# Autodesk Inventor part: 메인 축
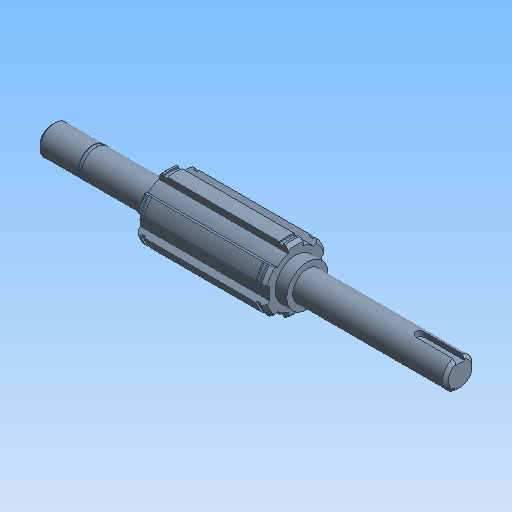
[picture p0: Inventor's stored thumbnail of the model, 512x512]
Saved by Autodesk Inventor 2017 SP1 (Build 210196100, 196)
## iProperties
Created: 2021-07
Part Number: 메인 축
Document SubType Name: 모델링
Designer: mdu
Mass: 168.566 g
Surface Area: 72.5104 cm^2
Volume: 21.4461 cm^3
Density: 7.86 g/cm^3
Material: 강철, 연강
Appearance: 연한 강청색
변환 표준: STEP AP214IS
파일 이름: C:\Users\SeoGD\Desktop\?쒗뿕\硫붿씤 異?.stp
전처리기: Build: 253, Release: 2010 SP1 - Date: Wed 07/29/2009
전송 단위: 밀리미터
불확실성: 0.01
Author: mdu
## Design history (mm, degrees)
sketch "스케치1"
  geometry: L1 (-69.5, 0)-(69.5, 0); L2 (69.5, 0)-(69.5, 5); L3 (69.5, 5)-(55.5, 5); L4 (55.5, 5)-(55.5, 4.8); L5 (55.5, 4.8)-(54.35, 4.8); L6 (54.35, 4.8)-(54.35, 5); L7 (54.35, 5)-(30.5, 5); L8 (30.5, 5)-(30.5, 9); L9 (30.5, 9)-(-13.5, 9); L10 (-13.5, 9)-(-13.5, 7); L11 (-13.5, 7)-(-17.5, 7); L12 (-17.5, 7)-(-17.5, 5); L13 (-17.5, 5)-(-69.5, 5); L14 (-69.5, 5)-(-69.5, 0); 2 further points
  constraints: 28 end point, 9 parallel, 4 collinear, 2 perpendicular, 1 coincident, 1 horizontal, 1 midpoint
  dimensions: "d2" = 1.15 distance between parallel lines of L6 L4; "d3" = 10 diameter of L3 L1; "d4" = 9.6 diameter of L5 L1; "d6" = 44 distance between parallel lines of L10 L8; "d7" = 4 distance between parallel lines of L12 L10; "d8" = 14 diameter of L11 L1; "d9" = 18 diameter of L9 L1; "d33" = 52 distance from line of L12.end L14; "d37" = 39 distance between parallel lines of L8 L2; "d38" = 14 distance between parallel lines of L2 L4
revolve "회전1" sketch "스케치1" stored, may be unused: angle "d10" = 90 deg
sketch "스케치2"
  geometry: L1 (2.5, 10.712)-(2.5, 8.646); L2 (-2.5, 10.712)-(-2.5, 8.646); A1 r 9 centre (0, 0) between (2.5, 8.646) and (-2.5, 8.646) reference; A2 r 11 centre (0, 0) between (2.5, 10.712) and (-2.5, 10.712); 1 further point
  constraints: 4 end point, 4 point on circle, 2 parallel, 1 centre point, 1 coincident, 1 vertical
  dimensions: "d11" = 22 diameter of A2; "d12" = 5 distance between parallel lines of L1 L2
extrude "돌출1" join sketch "스케치2" stored distance "d13" = 10; taper "d14" = 0 deg
chamfer "모따기1" distance "d15" = 1; stored, may be unused: second distance "d16" = 2, angle "d17" = 45 deg
node "작업 평면1"
node "작업 평면2"
sketch "스케치3"
  geometry: L1 (2.5, 10.712)-(2.5, 10.198); L2 (-2.5, 10.712)-(-2.5, 10.198); A1 r 11 centre (0, 0) between (2.5, 10.712) and (-2.5, 10.712) reference; A2 r 10.5 centre (0, 0) between (2.5, 10.198) and (-2.5, 10.198); 1 further point
  constraints: 4 end point, 2 point on circle, 1 centre point, 1 coincident, 1 parallel, 1 vertical
  dimensions: "d19" = 21 diameter of A2
extrude "돌출2" cut sketch "스케치3" distance "d20" = 1.35; taper "d21" = 0 deg
node "작업 평면3"
sketch "스케치4"
  geometry: L1 (-26, -5)-(-26, 5) reference; L2 (-26, 1.5)-(-12.5, 1.5); L3 (-12.5, -1.5)-(-26, -1.5); A1 r 1.5 centre (-12.5, 0) between (-12.5, -1.5) and (-12.5, 1.5); 2 further points
  constraints: 4 end point, 2 perpendicular, 2 point on circle, 2 point on line, 2 tangent, 1 centre point, 1 horizontal alignment, 1 midpoint
  dimensions: "d25" = 3 distance between parallel lines of L3 L2; "d26" = 15 dimension on A1 L1
extrude "돌출3" cut sketch "스케치4" distance "d27" = 1.8; taper "d28" = 0 deg
chamfer "모따기2" distance "d29" = 1; stored, may be unused: second distance "d30" = 2, angle "d31" = 45 deg
node "솔리드1"
node "솔리드 본체"
node "곡면 본체"
mirror "대칭1"
pattern_circular "원형 패턴1" dims "d23" = 360 deg
node "솔리드2"
other parameters: "d18" = -1.65
